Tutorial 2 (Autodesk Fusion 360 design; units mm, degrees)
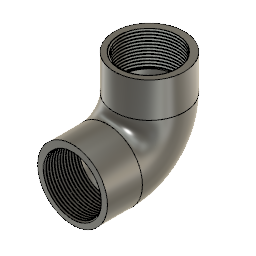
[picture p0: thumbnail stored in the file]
sketch "Sketch1" plane through (0, 0, 0) normal (1, 0, 0) x axis (0, 1, 0)
  line L1 (0, -50) -> (0, 0)
  line L2 (-110, -110) -> (-60, -110)
  arc A1 centre (-60, -50) radius 60 clockwise from (0, -50) to (-60, -110)
  point P1 (0, 0)
  point P2 (0, 0)
  point P3 (0, -50)
  point P4 (-60, -110)
  point P6 (-110, -110)
  coincident P1 P2
  vertical L1
  tangent L1 A1
  perpendicular L1 L2
  tangent A1 L2
  dimension "d1" distance P2 P3 = 50
  dimension "d2" radius A1 = 60
  dimension "d3" distance P4 P6 = 50
sketch "Sketch2" plane through (0, 0, 0) normal (0, 0, 1) x axis (1, 0, 0)
  circle C1 centre (0, 0) radius 50
  circle C2 centre (0, 0) radius 40.485
  point P1 (0, 0)
  point P2 (0, 0)
  point P3 (0, 0)
  coincident P1 P2
  coincident P1 P3
  dimension "d4" diameter C1 = 100
  dimension "d5" diameter C2 = 80.97
sweep "Sweep1" sketch "Sketch2" TwistAngle 0 TaperAngle 0
thread "Thread2"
